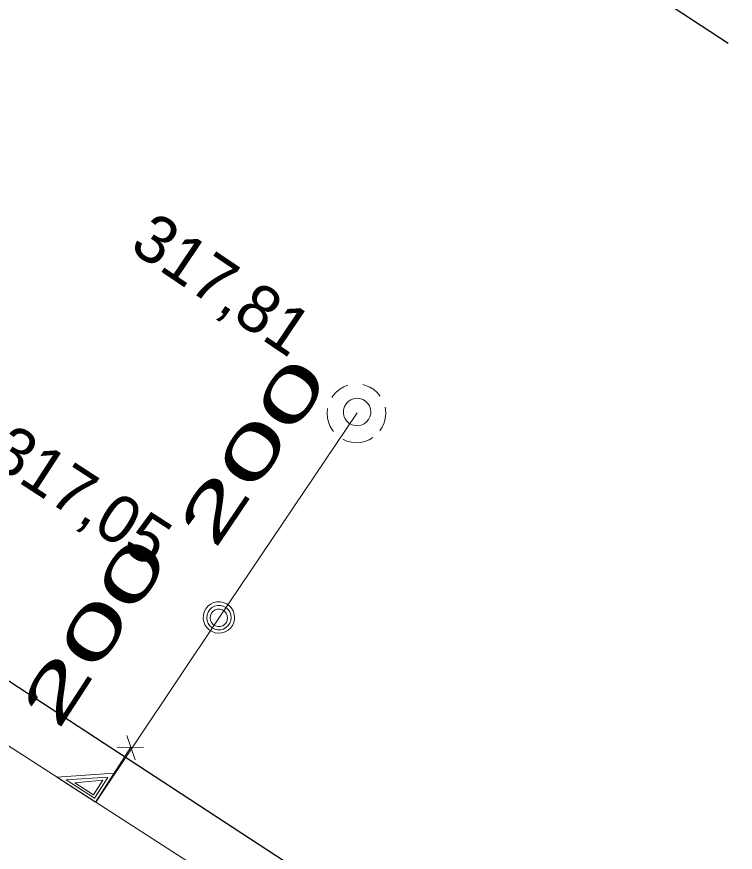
# Model space of a CAD drawing. Extents: x -742876 to -742577, y -1054710 to -1054452.
# Drawn here: x -742630.92 to -742618.85, y -1054539.95 to -1054525.92 of the extents above; entities that cross this region are included whole.
import ezdxf

# ---------------------------------------------------------------- set-up
doc = ezdxf.new("R2010")
doc.units = 0
doc.header["$LTSCALE"] = 0.36
doc.linetypes.add('MEDIUM_DASHED', pattern=[4.5, 3, -1.5])
for name, color, linetype, lineweight in [('1', 7, 'MEDIUM_DASHED', 25), ('18', 7, 'Continuous', 13), ('20', 7, 'Continuous', 13), ('49', 7, 'Continuous', 13), ('8', 7, 'Continuous', 13)]:
    doc.layers.add(name, color=color, linetype=linetype, lineweight=lineweight)

msp = doc.modelspace()

# ---------------------------------------------------------------- linework, layer by layer
at = {"layer": '1'}
msp.add_lwpolyline([(-742732.306, -1054452.031), (-742576.984, -1054553.898), (-742576.983, -1054553.899), (-742576.982, -1054553.901), (-742576.981, -1054553.903), (-742576.98, -1054553.905), (-742576.98, -1054553.907), (-742576.98, -1054553.909), (-742576.981, -1054553.91), (-742576.982, -1054553.912), (-742690.097, -1054710.32), (-742690.098, -1054710.321), (-742690.099, -1054710.322), (-742690.101, -1054710.323), (-742690.103, -1054710.324), (-742690.105, -1054710.324), (-742690.107, -1054710.324), (-742690.108, -1054710.323), (-742690.11, -1054710.322), (-742875.986, -1054593.411)], dxfattribs=at)
at = {"layer": '18'}
for p, q in [((-742629.064, -1054537.991), (-742628.928, -1054538.398)), ((-742628.786, -1054538.184), (-742629.23, -1054538.188))]:
    msp.add_line(p, q, dxfattribs=at)
for points in [[(-742625.352, -1054532.107), (-742625.423, -1054532.135), (-742625.49, -1054532.174), (-742625.55, -1054532.222), (-742625.601, -1054532.279), (-742625.625, -1054532.313)], [(-742624.811, -1054532.29), (-742624.861, -1054532.232), (-742624.919, -1054532.182), (-742624.984, -1054532.141), (-742625.055, -1054532.112), (-742625.104, -1054532.098)], [(-742624.816, -1054532.876), (-742624.775, -1054532.811), (-742624.744, -1054532.741), (-742624.725, -1054532.666), (-742624.717, -1054532.59), (-742624.722, -1054532.513), (-742624.728, -1054532.478)], [(-742625.697, -1054532.499), (-742625.703, -1054532.576), (-742625.698, -1054532.653), (-742625.681, -1054532.728), (-742625.652, -1054532.799), (-742625.612, -1054532.865), (-742625.596, -1054532.887)], [(-742625.439, -1054533.016), (-742625.369, -1054533.047), (-742625.294, -1054533.066), (-742625.218, -1054533.073), (-742625.141, -1054533.068), (-742625.066, -1054533.051), (-742624.994, -1054533.023), (-742624.934, -1054532.988)], [(-742628.999, -1054538.186), (-742629.593, -1054539.106), (-742630.24, -1054538.689), (-742629.279, -1054538.62)], [(-742629.386, -1054538.693), (-742629.611, -1054539.042), (-742630.086, -1054538.735), (-742629.385, -1054538.691)], [(-742629.47, -1054538.737), (-742629.629, -1054538.983), (-742629.941, -1054538.781), (-742629.469, -1054538.738)]]:
    msp.add_lwpolyline(points, dxfattribs=at)
for points in [[(-742624.968, -1054532.559), (-742624.974, -1054532.507), (-742624.992, -1054532.457), (-742625.02, -1054532.413), (-742625.058, -1054532.376), (-742625.103, -1054532.349), (-742625.153, -1054532.333), (-742625.205, -1054532.328), (-742625.257, -1054532.335), (-742625.306, -1054532.354), (-742625.35, -1054532.384), (-742625.385, -1054532.423), (-742625.411, -1054532.468), (-742625.426, -1054532.519), (-742625.429, -1054532.571), (-742625.421, -1054532.623), (-742625.4, -1054532.671), (-742625.37, -1054532.714), (-742625.33, -1054532.749), (-742625.284, -1054532.773), (-742625.233, -1054532.787), (-742625.181, -1054532.789), (-742625.129, -1054532.779), (-742625.081, -1054532.757), (-742625.039, -1054532.725), (-742625.006, -1054532.685), (-742624.982, -1054532.638), (-742624.97, -1054532.587)], [(-742627.256, -1054536.007), (-742627.262, -1054535.951), (-742627.279, -1054535.898), (-742627.308, -1054535.849), (-742627.346, -1054535.808), (-742627.392, -1054535.776), (-742627.444, -1054535.754), (-742627.499, -1054535.743), (-742627.555, -1054535.745), (-742627.61, -1054535.758), (-742627.661, -1054535.783), (-742627.705, -1054535.818), (-742627.741, -1054535.861), (-742627.766, -1054535.911), (-742627.781, -1054535.966), (-742627.784, -1054536.022), (-742627.775, -1054536.077), (-742627.754, -1054536.13), (-742627.723, -1054536.176), (-742627.683, -1054536.215), (-742627.635, -1054536.245), (-742627.582, -1054536.264), (-742627.526, -1054536.271), (-742627.47, -1054536.267), (-742627.416, -1054536.25), (-742627.367, -1054536.223), (-742627.325, -1054536.185), (-742627.292, -1054536.14), (-742627.269, -1054536.089), (-742627.257, -1054536.034)], [(-742627.315, -1054536.01), (-742627.321, -1054535.961), (-742627.339, -1054535.915), (-742627.367, -1054535.874), (-742627.404, -1054535.841), (-742627.448, -1054535.819), (-742627.496, -1054535.807), (-742627.545, -1054535.807), (-742627.593, -1054535.819), (-742627.637, -1054535.842), (-742627.674, -1054535.875), (-742627.702, -1054535.916), (-742627.719, -1054535.963), (-742627.725, -1054536.012), (-742627.718, -1054536.061), (-742627.7, -1054536.107), (-742627.672, -1054536.147), (-742627.635, -1054536.18), (-742627.591, -1054536.202), (-742627.542, -1054536.214), (-742627.493, -1054536.213), (-742627.445, -1054536.201), (-742627.402, -1054536.177), (-742627.365, -1054536.144), (-742627.337, -1054536.103), (-742627.321, -1054536.056)], [(-742627.374, -1054536.014), (-742627.38, -1054535.972), (-742627.397, -1054535.934), (-742627.425, -1054535.903), (-742627.46, -1054535.88), (-742627.5, -1054535.869), (-742627.542, -1054535.869), (-742627.582, -1054535.881), (-742627.617, -1054535.904), (-742627.644, -1054535.936), (-742627.661, -1054535.974), (-742627.666, -1054536.015), (-742627.66, -1054536.057), (-742627.642, -1054536.094), (-742627.614, -1054536.126), (-742627.578, -1054536.148), (-742627.538, -1054536.159), (-742627.496, -1054536.158), (-742627.456, -1054536.145), (-742627.422, -1054536.122), (-742627.395, -1054536.089), (-742627.379, -1054536.051)]]:
    msp.add_lwpolyline(points, close=True, dxfattribs=at)
at = {"layer": '20'}
msp.add_lwpolyline([(-742620.93, -1054544.69), (-742629.588, -1054539.108), (-742635.043, -1054535.591), (-742649.41, -1054526.33)], dxfattribs=at)
msp.add_lwpolyline([(-742620.93, -1054544.69), (-742629.588, -1054539.108), (-742635.043, -1054535.591), (-742649.41, -1054526.33)], dxfattribs=at)
at = {"layer": '49'}
for p, q in [((-742625.199, -1054532.57), (-742627.52, -1054536.02)), ((-742625.199, -1054532.57), (-742627.52, -1054536.02)), ((-742627.52, -1054536.02), (-742629.588, -1054539.108)), ((-742627.52, -1054536.02), (-742629.588, -1054539.108))]:
    msp.add_line(p, q, dxfattribs=at)
at = {"layer": '8', "lineweight": 25}
msp.add_lwpolyline([(-742635.66, -1054534.06), (-742617.61, -1054545.851), (-742608.91, -1054551.54), (-742608.609, -1054551.73), (-742608.42, -1054551.429)], dxfattribs=at)

# ---------------------------------------------------------------- texts
at = {"layer": '1'}
for s, rotation, p in [('317,81', 326, (-742629.045, -1054529.828)), ('317,05', 327, (-742631.415, -1054533.398))]:
    msp.add_text(s, height=0.8, rotation=rotation, dxfattribs=at).set_placement(p)
at = {"layer": '1', "width": 1.95}
for rotation, p in [(56, (-742627.594, -1054534.891)), (57, (-742630.225, -1054537.925))]:
    msp.add_text('200 ', height=0.8, rotation=rotation, dxfattribs=at).set_placement(p)

doc.saveas('drawing.dxf')
